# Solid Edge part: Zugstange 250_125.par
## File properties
Username: ahadarics
Dokumentum tartalom típus: 0
Author: ahadarics
Last saved by: ahadarics
Revision: 82
Sűrűség: 0,000 kg/m^3
Pontosság: 0,990
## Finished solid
Body 1: solid body, 5 faces, 7 edges, 4 vertices.
  Faces by surface: cone 2, plane 2, cylinder 1
  Edges by curve: circle 5, line 2
Bounding box of the edges (mm): 20.000 x 20.000 x 273.000, from (-10, -10, -186.5) to (10, 10, 86.5).
Cylindrical faces by radius (mm): R10 x1
Conical faces (half-angle, radius in mm at the cone's reference point): 45 deg R9.25 x2
Planar faces by outward normal: +z 1, -z 1
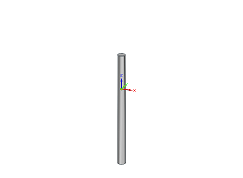
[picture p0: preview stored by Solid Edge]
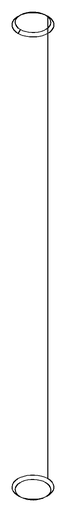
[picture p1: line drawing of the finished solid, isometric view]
